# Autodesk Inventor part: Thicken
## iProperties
Shininess: 64.0
Length Units: 11269
Angle Units: 11279
Time Units: 11290
Mass Units: 11283
Length Display Precision: 3
Angle Display Precision: 2
Compacted: True
Part Number: Thicken
Document SubType Name: Modeling
Created: 2002-12
Designer: deepak
Density: 1 g/cm^3
Density: 0.0
Volumn: 0.0
Area: 0.0
PropertySet Name: Model Information
Control State: 0
Master: False
Checked Out: False
Author: deepak
